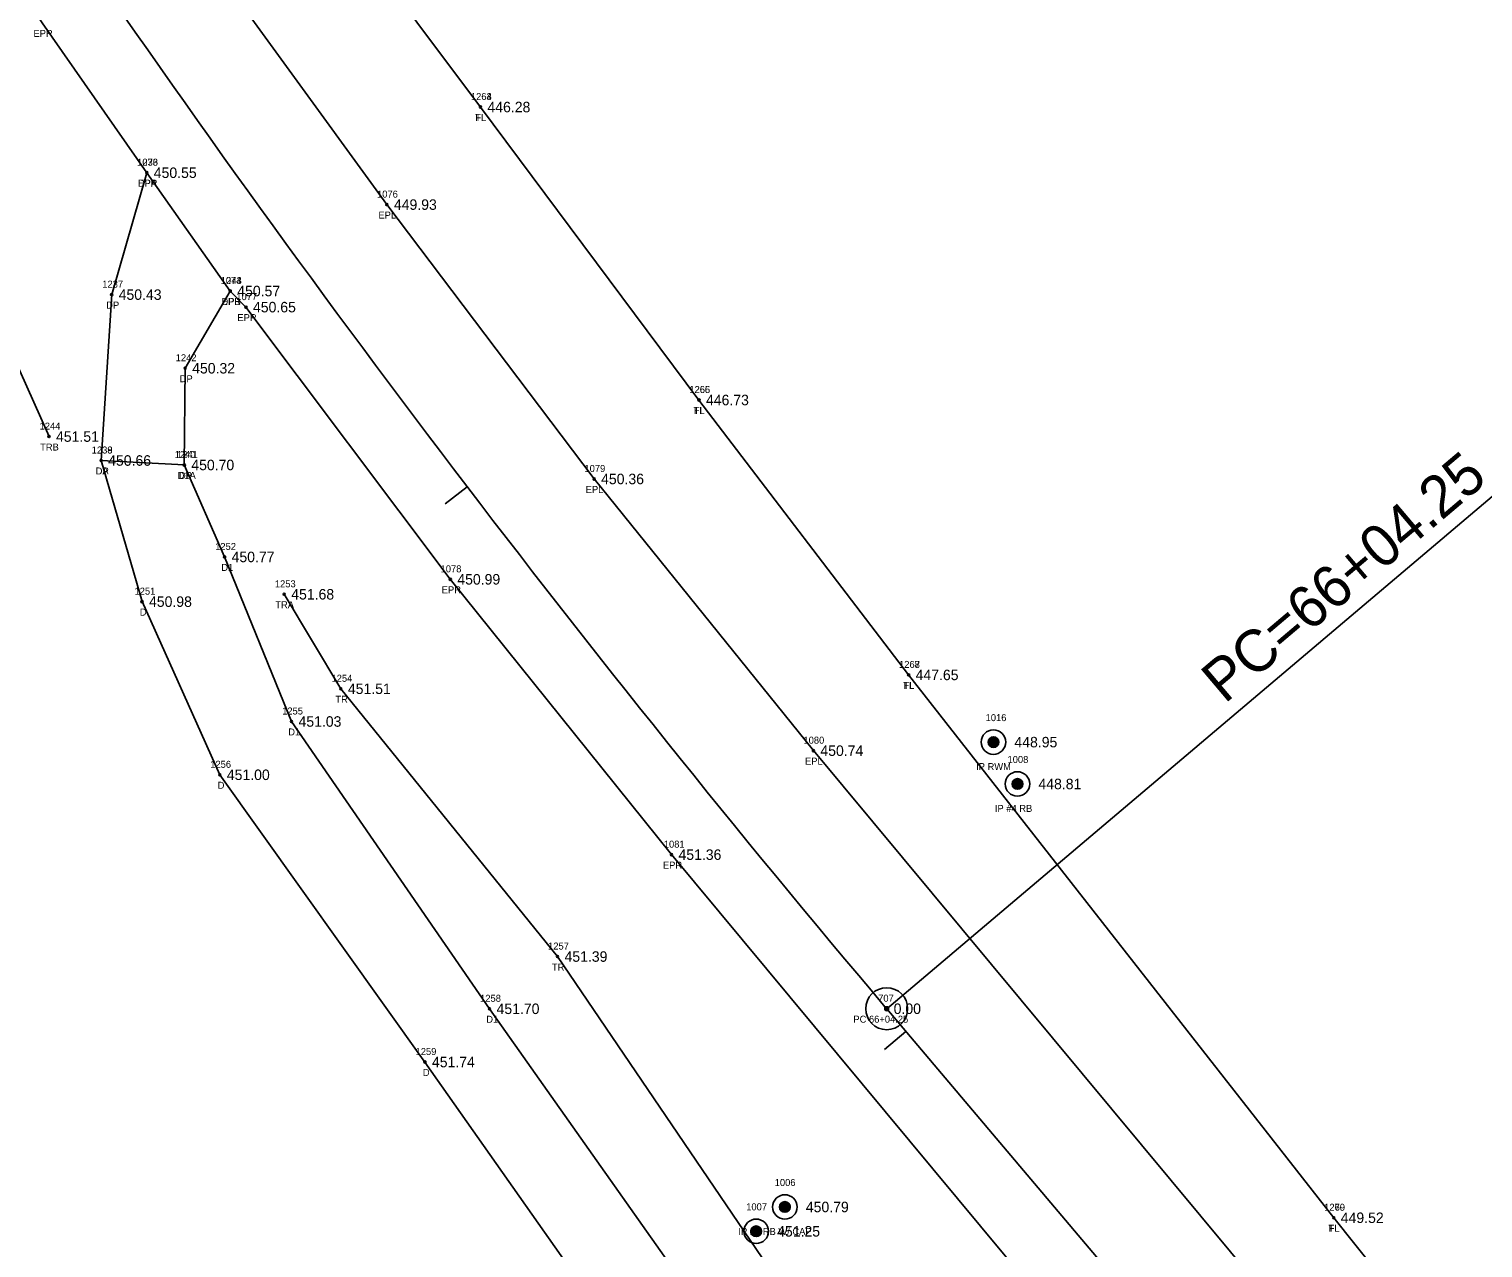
# Model space of a CAD drawing. Extents: x 1745838 to 1751416, y 649214 to 655806.
# Drawn here: x 1748785.5 to 1748993.4, y 651653.4 to 651827.7 of the extents above; entities that cross this region are included whole.
import ezdxf

# ---------------------------------------------------------------- set-up
doc = ezdxf.new("R2010")
doc.units = 0
for name, color, linetype in [('RD_EX_Driveway', 7, 'Continuous'), ('RD_EX_Driveway_txCode', 7, 'Continuous'), ('RD_EX_DV_Prop_txCode', 7, 'Continuous'), ('RD_EX_DV_PropPin', 7, 'Continuous'), ('RD_EX_Fence_Other', 7, 'Continuous'), ('RD_EX_Fence_Other_txCode', 7, 'Continuous'), ('RD_EX_Road', 7, 'Continuous'), ('RD_EX_Road_txCode', 7, 'Continuous'), ('RD_EX_TX_Driveway_ELEV', 7, 'Continuous'), ('RD_EX_TX_DV_Prop_ELEV', 7, 'Continuous'), ('RD_EX_TX_Fence_Other_ELEV', 7, 'Continuous'), ('RD_EX_TX_Road_ELEV', 7, 'Continuous'), ('RD_EX_TX_VEG_ELEV', 7, 'Continuous'), ('RD_EX_VEG', 7, 'Continuous'), ('RD_EX_VEG_txCode', 7, 'Continuous'), ('RD_HC_Cl', 7, 'Continuous'), ('RD_HC_Data', 7, 'Continuous'), ('RD_HC_Data_Tic', 7, 'Continuous'), ('RD_HC_Survey_ELEV', 7, 'Continuous'), ('RD_HC_txCode', 7, 'Continuous'), ('RD_SMD_Locator', 7, 'Continuous')]:
    doc.layers.add(name, color=color, linetype=linetype)

msp = doc.modelspace()

# ---------------------------------------------------------------- linework, layer by layer
at = {"layer": 'RD_EX_Driveway'}
for points in [[(1748802.29, 651807.16), (1748797.27, 651789.73), (1748795.77, 651766.01), (1748807.66, 651765.37), (1748807.78, 651779.2), (1748814.23, 651790.24)], [(1748795.77, 651766.01), (1748801.61, 651745.83), (1748812.74, 651721.07), (1748842.07, 651680), (1748901.43, 651595.63), (1748937.78, 651558.5), (1748964.16, 651514.33), (1748958.37, 651494.63)], [(1748807.66, 651765.37), (1748813.42, 651752.22), (1748822.99, 651728.69), (1748851.31, 651687.61), (1748910.63, 651603.57), (1748947.5, 651567.98), (1748979.72, 651522.75), (1748978.03, 651507.44), (1748964.94, 651487.94)]]:
    msp.add_lwpolyline(points, dxfattribs=at)
at = {"layer": 'RD_EX_DV_PropPin'}
for p, q in [((1748922.78, 651725.27), (1748922.78, 651726.22)), ((1748922.81, 651725.23), (1748922.81, 651726.26)), ((1748922.85, 651725.19), (1748922.85, 651726.29)), ((1748922.88, 651725.16), (1748922.88, 651726.33)), ((1748922.92, 651725.13), (1748922.92, 651726.35)), ((1748922.95, 651725.11), (1748922.95, 651726.38)), ((1748922.99, 651725.09), (1748922.99, 651726.4)), ((1748923.02, 651725.07), (1748923.02, 651726.42)), ((1748923.06, 651725.05), (1748923.06, 651726.44)), ((1748923.09, 651725.04), (1748923.09, 651726.45)), ((1748923.13, 651725.02), (1748923.13, 651726.46)), ((1748923.16, 651725.01), (1748923.16, 651726.47)), ((1748923.2, 651725), (1748923.2, 651726.48)), ((1748923.23, 651725), (1748923.23, 651726.49)), ((1748923.27, 651724.99), (1748923.27, 651726.5)), ((1748923.3, 651724.99), (1748923.3, 651726.5)), ((1748923.34, 651724.98), (1748923.34, 651726.5)), ((1748923.37, 651724.98), (1748923.37, 651726.5)), ((1748923.41, 651724.98), (1748923.41, 651726.5)), ((1748923.44, 651724.99), (1748923.44, 651726.5)), ((1748923.48, 651724.99), (1748923.48, 651726.5)), ((1748923.51, 651725), (1748923.51, 651726.49)), ((1748923.55, 651725), (1748923.55, 651726.48)), ((1748923.58, 651725.01), (1748923.58, 651726.47)), ((1748923.62, 651725.02), (1748923.62, 651726.46)), ((1748923.65, 651725.04), (1748923.65, 651726.45)), ((1748923.69, 651725.05), (1748923.69, 651726.44)), ((1748923.72, 651725.07), (1748923.72, 651726.42)), ((1748923.76, 651725.09), (1748923.76, 651726.4)), ((1748923.79, 651725.11), (1748923.79, 651726.38)), ((1748923.83, 651725.13), (1748923.83, 651726.35)), ((1748923.86, 651725.16), (1748923.86, 651726.33)), ((1748923.9, 651725.19), (1748923.9, 651726.29)), ((1748923.93, 651725.23), (1748923.93, 651726.26)), ((1748923.97, 651725.27), (1748923.97, 651726.22)), ((1748922.64, 651725.55), (1748922.64, 651725.94)), ((1748922.67, 651725.45), (1748922.67, 651726.04)), ((1748922.71, 651725.37), (1748922.71, 651726.11)), ((1748922.74, 651725.32), (1748922.74, 651726.17)), ((1748924, 651725.32), (1748924, 651726.17)), ((1748924.04, 651725.37), (1748924.04, 651726.11)), ((1748924.07, 651725.45), (1748924.07, 651726.04)), ((1748924.11, 651725.55), (1748924.11, 651725.94)), ((1748926.07, 651719.56), (1748926.07, 651719.95)), ((1748926.1, 651719.46), (1748926.1, 651720.05)), ((1748926.14, 651719.39), (1748926.14, 651720.13)), ((1748926.17, 651719.33), (1748926.17, 651720.18)), ((1748926.21, 651719.28), (1748926.21, 651720.23)), ((1748926.24, 651719.24), (1748926.24, 651720.27)), ((1748926.28, 651719.21), (1748926.28, 651720.31)), ((1748926.31, 651719.17), (1748926.31, 651720.34)), ((1748926.35, 651719.15), (1748926.35, 651720.37)), ((1748926.38, 651719.12), (1748926.38, 651720.39)), ((1748926.42, 651719.1), (1748926.42, 651720.41)), ((1748926.45, 651719.08), (1748926.45, 651720.43)), ((1748926.49, 651719.06), (1748926.49, 651720.45)), ((1748926.52, 651719.05), (1748926.52, 651720.46)), ((1748926.56, 651719.04), (1748926.56, 651720.48)), ((1748926.59, 651719.02), (1748926.59, 651720.49)), ((1748926.63, 651719.02), (1748926.63, 651720.5)), ((1748926.66, 651719.01), (1748926.66, 651720.5)), ((1748926.7, 651719), (1748926.7, 651720.51)), ((1748926.73, 651719), (1748926.73, 651720.51)), ((1748926.77, 651719), (1748926.77, 651720.52)), ((1748926.8, 651719), (1748926.8, 651720.52)), ((1748926.84, 651719), (1748926.84, 651720.52)), ((1748926.87, 651719), (1748926.87, 651720.51)), ((1748926.91, 651719), (1748926.91, 651720.51)), ((1748926.94, 651719.01), (1748926.94, 651720.5)), ((1748926.98, 651719.02), (1748926.98, 651720.5)), ((1748927.01, 651719.02), (1748927.01, 651720.49)), ((1748927.05, 651719.04), (1748927.05, 651720.48)), ((1748927.08, 651719.05), (1748927.08, 651720.46)), ((1748927.12, 651719.06), (1748927.12, 651720.45)), ((1748927.15, 651719.08), (1748927.15, 651720.43)), ((1748927.19, 651719.1), (1748927.19, 651720.41)), ((1748927.22, 651719.12), (1748927.22, 651720.39)), ((1748927.26, 651719.15), (1748927.26, 651720.37)), ((1748927.29, 651719.17), (1748927.29, 651720.34)), ((1748927.33, 651719.21), (1748927.33, 651720.31)), ((1748927.36, 651719.24), (1748927.36, 651720.27)), ((1748927.4, 651719.28), (1748927.4, 651720.23)), ((1748927.43, 651719.33), (1748927.43, 651720.18)), ((1748927.47, 651719.39), (1748927.47, 651720.13)), ((1748927.5, 651719.46), (1748927.5, 651720.05)), ((1748927.54, 651719.56), (1748927.54, 651719.95)), ((1748892.88, 651658.9), (1748892.88, 651659.64)), ((1748892.91, 651658.85), (1748892.91, 651659.7)), ((1748892.95, 651658.8), (1748892.95, 651659.75)), ((1748892.98, 651658.76), (1748892.98, 651659.79)), ((1748893.02, 651658.72), (1748893.02, 651659.83)), ((1748893.05, 651658.69), (1748893.05, 651659.86)), ((1748893.09, 651658.66), (1748893.09, 651659.88)), ((1748893.12, 651658.64), (1748893.12, 651659.91)), ((1748893.16, 651658.62), (1748893.16, 651659.93)), ((1748893.19, 651658.6), (1748893.19, 651659.95)), ((1748893.23, 651658.58), (1748893.23, 651659.97)), ((1748893.26, 651658.57), (1748893.26, 651659.98)), ((1748893.3, 651658.55), (1748893.3, 651659.99)), ((1748893.33, 651658.54), (1748893.33, 651660.01)), ((1748893.37, 651658.53), (1748893.37, 651660.02)), ((1748893.4, 651658.53), (1748893.4, 651660.02)), ((1748893.44, 651658.52), (1748893.44, 651660.03)), ((1748893.47, 651658.52), (1748893.47, 651660.03)), ((1748893.51, 651658.51), (1748893.51, 651660.03)), ((1748893.54, 651658.51), (1748893.54, 651660.04)), ((1748893.58, 651658.51), (1748893.58, 651660.03)), ((1748893.61, 651658.52), (1748893.61, 651660.03)), ((1748893.65, 651658.52), (1748893.65, 651660.03)), ((1748893.68, 651658.53), (1748893.68, 651660.02)), ((1748893.72, 651658.53), (1748893.72, 651660.02)), ((1748893.75, 651658.54), (1748893.75, 651660.01)), ((1748893.79, 651658.55), (1748893.79, 651659.99)), ((1748893.82, 651658.57), (1748893.82, 651659.98)), ((1748893.86, 651658.58), (1748893.86, 651659.97)), ((1748893.89, 651658.6), (1748893.89, 651659.95)), ((1748893.93, 651658.62), (1748893.93, 651659.93)), ((1748893.96, 651658.64), (1748893.96, 651659.91)), ((1748894, 651658.66), (1748894, 651659.88)), ((1748894.03, 651658.69), (1748894.03, 651659.86)), ((1748894.07, 651658.72), (1748894.07, 651659.83)), ((1748894.1, 651658.76), (1748894.1, 651659.79)), ((1748894.14, 651658.8), (1748894.14, 651659.75)), ((1748894.17, 651658.85), (1748894.17, 651659.7)), ((1748894.21, 651658.9), (1748894.21, 651659.64)), ((1748892.81, 651659.08), (1748892.81, 651659.47)), ((1748892.84, 651658.98), (1748892.84, 651659.57)), ((1748894.24, 651658.98), (1748894.24, 651659.57)), ((1748894.28, 651659.08), (1748894.28, 651659.47)), ((1748888.7, 651655.6), (1748888.7, 651655.99)), ((1748888.74, 651655.49), (1748888.74, 651656.09)), ((1748888.77, 651655.42), (1748888.77, 651656.16)), ((1748888.81, 651655.36), (1748888.81, 651656.22)), ((1748888.84, 651655.32), (1748888.84, 651656.27)), ((1748888.88, 651655.28), (1748888.88, 651656.31)), ((1748888.91, 651655.24), (1748888.91, 651656.34)), ((1748888.95, 651655.21), (1748888.95, 651656.37)), ((1748888.98, 651655.18), (1748888.98, 651656.4)), ((1748889.02, 651655.16), (1748889.02, 651656.43)), ((1748889.05, 651655.14), (1748889.05, 651656.45)), ((1748889.09, 651655.12), (1748889.09, 651656.47)), ((1748889.12, 651655.1), (1748889.12, 651656.48)), ((1748889.16, 651655.08), (1748889.16, 651656.5)), ((1748889.19, 651655.07), (1748889.19, 651656.51)), ((1748889.23, 651655.06), (1748889.23, 651656.52)), ((1748889.26, 651655.05), (1748889.26, 651656.53)), ((1748889.3, 651655.04), (1748889.3, 651656.54)), ((1748889.33, 651655.04), (1748889.33, 651656.55)), ((1748889.37, 651655.03), (1748889.37, 651656.55)), ((1748889.4, 651655.03), (1748889.4, 651656.55)), ((1748889.44, 651655.03), (1748889.44, 651656.55)), ((1748889.47, 651655.03), (1748889.47, 651656.55)), ((1748889.51, 651655.03), (1748889.51, 651656.55)), ((1748889.54, 651655.04), (1748889.54, 651656.55)), ((1748889.58, 651655.04), (1748889.58, 651656.54)), ((1748889.61, 651655.05), (1748889.61, 651656.53)), ((1748889.65, 651655.06), (1748889.65, 651656.52)), ((1748889.68, 651655.07), (1748889.68, 651656.51)), ((1748889.72, 651655.08), (1748889.72, 651656.5)), ((1748889.75, 651655.1), (1748889.75, 651656.48)), ((1748889.79, 651655.12), (1748889.79, 651656.47)), ((1748889.82, 651655.14), (1748889.82, 651656.45)), ((1748889.86, 651655.16), (1748889.86, 651656.43)), ((1748889.89, 651655.18), (1748889.89, 651656.4)), ((1748889.93, 651655.21), (1748889.93, 651656.37)), ((1748889.96, 651655.24), (1748889.96, 651656.34)), ((1748890, 651655.28), (1748890, 651656.31)), ((1748890.03, 651655.32), (1748890.03, 651656.27)), ((1748890.07, 651655.36), (1748890.07, 651656.22)), ((1748890.1, 651655.42), (1748890.1, 651656.16)), ((1748890.14, 651655.49), (1748890.14, 651656.09)), ((1748890.17, 651655.6), (1748890.17, 651655.99))]:
    msp.add_line(p, q, dxfattribs=at)
for centre, radius in [((1748923.37, 651725.74), 1.75), ((1748923.37, 651725.74), 0.761), ((1748926.8, 651719.76), 1.75), ((1748926.8, 651719.76), 0.761), ((1748893.54, 651659.27), 1.75), ((1748893.54, 651659.27), 0.761), ((1748889.44, 651655.79), 1.75), ((1748889.44, 651655.79), 0.761)]:
    msp.add_circle(centre, radius, dxfattribs=at)
at = {"layer": 'RD_EX_Fence_Other'}
msp.add_lwpolyline([(1748731.62, 652100.81), (1748735.3, 652085.13), (1748740.66, 652074.74), (1748752.07, 652055.81), (1748751.12, 652043.36), (1748750.95, 652030.95), (1748767.27, 651998.87), (1748767.27, 651998.87), (1748762.01, 651980.2), (1748768.15, 651939.38), (1748794.06, 651893.44), (1748822.68, 651853.02), (1748850.01, 651816.55), (1748881.26, 651774.66), (1748911.24, 651735.35), (1748972.04, 651657.73), (1749035.87, 651577.68), (1749083.16, 651517.4), (1749096.96, 651526.43)], dxfattribs=at)
at = {"layer": 'RD_EX_Road'}
for points in [[(1748430.72, 652573.59), (1748472.3, 652485.07), (1748515.54, 652394.24), (1748548.4, 652323.99), (1748589.23, 652237.29), (1748607.12, 652198.86), (1748609.09, 652199.5), (1748633.39, 652147.73), (1748655.85, 652100.41), (1748677.16, 652057.64), (1748701.06, 652012.63), (1748725.12, 651970.47), (1748751.23, 651927.26), (1748777.84, 651886.08), (1748807.14, 651843.17), (1748836.63, 651802.6), (1748866.26, 651763.37), (1748897.62, 651724.52), (1748961.52, 651647.76), (1748997.97, 651603.49), (1749026.31, 651569.66), (1749088.99, 651495.68)], [(1748586.63, 652188.46), (1748610.53, 652136.78), (1748632.69, 652090.17), (1748654.96, 652046.55), (1748679.12, 652001.12), (1748703.77, 651957.47), (1748729.93, 651914.24), (1748757.13, 651872.56), (1748787.32, 651828.58), (1748802.29, 651807.16), (1748814.23, 651790.24), (1748816.48, 651787.94), (1748845.7, 651749.02), (1748877.33, 651709.65), (1748941.98, 651631.92), (1748980.41, 651586.71), (1749008.3, 651553.67), (1749070.58, 651479.58), (1749079.79, 651486.92), (1749088.99, 651495.68)]]:
    msp.add_lwpolyline(points, dxfattribs=at)
at = {"layer": 'RD_EX_VEG'}
for points in [[(1748400.28, 652560.72), (1748444.25, 652470.71), (1748481.68, 652376.84), (1748519.88, 652309.17), (1748561.49, 652223.46), (1748604.12, 652134.28), (1748614.3, 652082.38), (1748634.9, 652033.68), (1748660.67, 651990.85), (1748689.7, 651948.01), (1748715.77, 651906.01), (1748741.05, 651861.36), (1748767.74, 651815.44), (1748788.31, 651769.43)], [(1748727.21, 652033.07), (1748719.78, 652021.13), (1748741.73, 651976.11), (1748768.15, 651939.38), (1748794.06, 651893.44), (1748822.68, 651853.02), (1748850.01, 651816.55), (1748881.26, 651774.66), (1748911.24, 651735.35), (1748972.04, 651657.73), (1749035.87, 651577.68), (1749102.17, 651496.37), (1749126.54, 651516.47), (1749148.35, 651529.92), (1749165.73, 651545.44)], [(1748821.95, 651746.88), (1748830.05, 651733.37), (1748861.03, 651695.08), (1748918.76, 651610.1), (1748983.82, 651532.58), (1749046.48, 651476.99), (1749050.27, 651445.74), (1749011.3, 651414.42)]]:
    msp.add_lwpolyline(points, dxfattribs=at)
at = {"layer": 'RD_HC_Cl'}
msp.add_line((1749546.44, 650932.91), (1748908.1, 651687.62), dxfattribs=at)
msp.add_arc((1750366.33, 652921.01), 1909.89, 208.35249, 220.22476, dxfattribs=at)
at = {"layer": 'RD_HC_Data'}
msp.add_line((1748908.1, 651687.62), (1748997.15, 651762.95), dxfattribs=at)
for radius in [3, 0.282]:
    msp.add_circle((1748908.1, 651687.62), radius, dxfattribs=at)
at = {"layer": 'RD_HC_Data_Tic'}
for p, q in [((1748848.12, 651762.25), (1748844.94, 651759.82)), ((1748910.84, 651684.38), (1748907.79, 651681.79))]:
    msp.add_line(p, q, dxfattribs=at)
at = {"layer": 'RD_SMD_Locator'}
for centre in [(1748850.01, 651816.55), (1748850.01, 651816.55), (1748802.29, 651807.16), (1748802.29, 651807.16), (1748836.63, 651802.6), (1748797.27, 651789.73), (1748814.23, 651790.24), (1748814.23, 651790.24), (1748816.48, 651787.94), (1748807.78, 651779.2), (1748881.26, 651774.66), (1748881.26, 651774.66), (1748788.31, 651769.43), (1748795.77, 651766.01), (1748795.77, 651766.01), (1748807.66, 651765.37), (1748807.66, 651765.37), (1748866.26, 651763.37), (1748813.42, 651752.22), (1748845.7, 651749.02), (1748821.95, 651746.88), (1748801.61, 651745.83), (1748911.24, 651735.35), (1748911.24, 651735.35), (1748830.05, 651733.37), (1748822.99, 651728.69), (1748897.62, 651724.52), (1748923.37, 651725.74), (1748812.74, 651721.07), (1748926.8, 651719.76), (1748877.33, 651709.65), (1748861.03, 651695.08), (1748851.31, 651687.61), (1748908.1, 651687.62), (1748842.07, 651680), (1748893.54, 651659.27), (1748972.04, 651657.73), (1748972.04, 651657.73), (1748889.44, 651655.79)]:
    msp.add_circle(centre, 0.15, dxfattribs=at)

# ---------------------------------------------------------------- texts
at = {"layer": 'RD_EX_Driveway_txCode'}
for s, p in [('1236', (1748800.92, 651808.16)), ('DPA', (1748801.02, 651805.16)), ('1237', (1748795.93, 651790.73)), ('1243', (1748812.89, 651791.24)), ('DP', (1748796.49, 651787.73)), ('DPB', (1748812.98, 651788.24)), ('1242', (1748806.43, 651780.2)), ('DP', (1748807, 651777.2)), ('1238', (1748794.42, 651767.01)), ('1239', (1748794.42, 651767.01)), ('1240', (1748806.28, 651766.37)), ('1241', (1748806.6, 651766.37)), ('DA', (1748794.97, 651764.01)), ('DP', (1748794.99, 651764.01)), ('D1A', (1748806.7, 651763.37)), ('DP', (1748806.89, 651763.37)), ('1252', (1748812.07, 651753.22)), ('D1', (1748812.95, 651750.22)), ('1251', (1748800.54, 651746.83)), ('D', (1748801.3, 651743.83)), ('1255', (1748821.65, 651729.69)), ('D1', (1748822.52, 651726.69)), ('1256', (1748811.37, 651722.07)), ('D', (1748812.43, 651719.07)), ('1258', (1748849.96, 651688.61)), ('D1', (1748850.84, 651685.61)), ('1259', (1748840.73, 651681)), ('D', (1748841.77, 651678))]:
    msp.add_text(s, height=1, dxfattribs=at).set_placement(p)
at = {"layer": 'RD_EX_DV_Prop_txCode'}
for s, p in [('1016', (1748922.25, 651728.74)), ('IP RWM', (1748920.89, 651721.74)), ('1008', (1748925.38, 651722.76)), ('IP #4 RB', (1748923.57, 651715.76)), ('1006', (1748892.09, 651662.27)), ('1007', (1748888.01, 651658.79)), ('IP #4 RB W/ CAP', (1748886.89, 651655.27))]:
    msp.add_text(s, height=1, dxfattribs=at).set_placement(p)
at = {"layer": 'RD_EX_Fence_Other_txCode'}
for s, p in [('1263', (1748848.64, 651817.55)), ('FL', (1748849.28, 651814.55)), ('1265', (1748879.89, 651775.66)), ('FL', (1748880.53, 651772.66)), ('1268', (1748909.87, 651736.35)), ('FL', (1748910.51, 651733.35)), ('1270', (1748970.66, 651658.73)), ('FL', (1748971.31, 651655.73))]:
    msp.add_text(s, height=1, dxfattribs=at).set_placement(p)
at = {"layer": 'RD_EX_Road_txCode'}
for s, p in [('EPR', (1748786.09, 651826.58)), ('1073', (1748800.91, 651808.16)), ('EPR', (1748801.06, 651805.16)), ('1076', (1748835.22, 651803.6)), ('EPL', (1748835.42, 651800.6)), ('1074', (1748812.85, 651791.24)), ('EPR', (1748813, 651788.24)), ('1077', (1748815.09, 651788.94)), ('EPR', (1748815.25, 651785.94)), ('1079', (1748864.88, 651764.37)), ('EPL', (1748865.06, 651761.37)), ('1078', (1748844.31, 651750.02)), ('EPR', (1748844.47, 651747.02)), ('1080', (1748896.2, 651725.52)), ('EPL', (1748896.42, 651722.52)), ('1081', (1748876.23, 651710.65)), ('EPR', (1748876.1, 651707.65))]:
    msp.add_text(s, height=1, dxfattribs=at).set_placement(p)
at = {"layer": 'RD_EX_TX_Driveway_ELEV'}
for s, p in [('450.55', (1748803.29, 651806.41)), ('450.57', (1748815.23, 651789.49)), ('450.43', (1748798.27, 651788.98)), ('450.32', (1748808.78, 651778.45)), ('450.66', (1748796.77, 651765.26)), ('450.66', (1748796.77, 651765.26)), ('450.70', (1748808.66, 651764.62)), ('450.70', (1748808.66, 651764.62)), ('450.77', (1748814.42, 651751.47)), ('450.98', (1748802.61, 651745.08)), ('451.03', (1748823.99, 651727.94)), ('451.00', (1748813.74, 651720.32)), ('451.70', (1748852.31, 651686.86)), ('451.74', (1748843.07, 651679.25))]:
    msp.add_text(s, height=1.5, dxfattribs=at).set_placement(p)
at = {"layer": 'RD_EX_TX_DV_Prop_ELEV'}
for s, p in [('448.95', (1748926.37, 651724.99)), ('448.81', (1748929.8, 651719.01)), ('450.79', (1748896.54, 651658.52)), ('451.25', (1748892.44, 651655.04))]:
    msp.add_text(s, height=1.5, dxfattribs=at).set_placement(p)
at = {"layer": 'RD_EX_TX_Fence_Other_ELEV'}
for s, p in [('446.28', (1748851.01, 651815.8)), ('446.73', (1748882.26, 651773.91)), ('447.65', (1748912.24, 651734.6)), ('449.52', (1748973.04, 651656.98))]:
    msp.add_text(s, height=1.5, dxfattribs=at).set_placement(p)
at = {"layer": 'RD_EX_TX_Road_ELEV'}
for s, p in [('450.55', (1748803.29, 651806.41)), ('449.93', (1748837.63, 651801.85)), ('450.57', (1748815.23, 651789.49)), ('450.65', (1748817.48, 651787.19)), ('450.36', (1748867.26, 651762.62)), ('450.99', (1748846.7, 651748.27)), ('450.74', (1748898.62, 651723.77)), ('451.36', (1748878.33, 651708.9))]:
    msp.add_text(s, height=1.5, dxfattribs=at).set_placement(p)
at = {"layer": 'RD_EX_TX_VEG_ELEV'}
for s, p in [('446.28', (1748851.01, 651815.8)), ('446.73', (1748882.26, 651773.91)), ('451.51', (1748789.31, 651768.68)), ('451.68', (1748822.95, 651746.13)), ('447.65', (1748912.24, 651734.6)), ('451.51', (1748831.05, 651732.62)), ('451.39', (1748862.03, 651694.33)), ('449.52', (1748973.04, 651656.98))]:
    msp.add_text(s, height=1.5, dxfattribs=at).set_placement(p)
at = {"layer": 'RD_EX_VEG_txCode'}
for s, p in [('1264', (1748848.64, 651817.55)), ('TL', (1748849.24, 651814.55)), ('1266', (1748879.87, 651775.66)), ('TL', (1748880.49, 651772.66)), ('1244', (1748786.96, 651770.43)), ('TRB', (1748787.04, 651767.43)), ('1253', (1748820.61, 651747.88)), ('TRA', (1748820.67, 651744.88)), ('1267', (1748909.87, 651736.35)), ('1254', (1748828.71, 651734.37)), ('TL', (1748910.47, 651733.35)), ('TR', (1748829.26, 651731.37)), ('1257', (1748859.68, 651696.08)), ('TR', (1748860.23, 651693.08)), ('1269', (1748970.67, 651658.73)), ('TL', (1748971.27, 651655.73))]:
    msp.add_text(s, height=1, dxfattribs=at).set_placement(p)
at = {"layer": 'RD_HC_Data'}
msp.add_text('PC=66+04.25', height=6, rotation=40.2248, dxfattribs=at).set_placement((1748956.43, 651731.13))
at = {"layer": 'RD_HC_Survey_ELEV'}
msp.add_text('0.00', height=1.5, dxfattribs=at).set_placement((1748909.1, 651686.87))
at = {"layer": 'RD_HC_txCode'}
for s, p in [('707', (1748906.88, 651688.62)), ('PC 66+04.25', (1748903.34, 651685.62))]:
    msp.add_text(s, height=1, dxfattribs=at).set_placement(p)

doc.saveas('drawing.dxf')
